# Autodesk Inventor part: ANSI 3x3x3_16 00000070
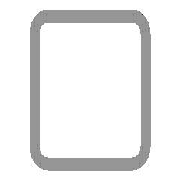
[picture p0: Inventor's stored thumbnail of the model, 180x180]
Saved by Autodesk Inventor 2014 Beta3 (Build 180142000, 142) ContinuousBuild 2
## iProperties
IsCustomPart: 1
_CCFamilyMember: 9
_CCFamilyDisplayName: ANSI AISC (Square) - Tube
_FrameMemberDoc: Frame Member File
_Version: 15.0.0
_GetPNFromCC: 1
Created: 2010-11
Part Number: ANSI 3x3x3_16 00000070
Material: Steel, Mild
Description: Tube
Document SubType Name: Modeling
Standard: ANSI
Designer: Beta-8540w
Standards Organization: ANSI
Language: en-US
Size Designation: 3x3x3/16
Categories: <MemberInstance><Categories><Category DisplayName="Structural Shapes" InternalName="089c4875-fa83-4c05-b084-43b9cc11f5ed" Mnemonic="GRDR"><CategoryParameter Dis
Stock Number: 3x3x3/16
Density: 7.86 g/cm^3
Appearance: Steel
G_L: 16.000 in
G_W: 3.000 in
G_H: 3.000 in
Author: Beta-8540w
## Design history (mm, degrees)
node "Start plane"
node "End plane"
sketch "Sketch"
  geometry: L1 (-38.1, -28.575)-(-38.1, 28.575); L2 (-28.575, 38.1)-(28.575, 38.1); L3 (38.1, 28.575)-(38.1, -28.575); L4 (28.575, -38.1)-(-28.575, -38.1); L5 (-28.575, 33.337)-(28.575, 33.338); L6 (33.338, 28.575)-(33.338, -28.575); L7 (28.575, -33.337)-(-28.575, -33.338); L8 (-33.338, -28.575)-(-33.338, 28.575); L9 (0, 56.102)-(0, -56.102) reference; L10 (-56.102, 0)-(56.102, 0) reference; A1 r 9.525 centre (-28.575, -28.575) between (-38.1, -28.575) and (-28.575, -38.1); A2 r 9.525 centre (-28.575, 28.575) between (-28.575, 38.1) and (-38.1, 28.575); A3 r 9.525 centre (28.575, 28.575) between (38.1, 28.575) and (28.575, 38.1); A4 r 9.525 centre (28.575, -28.575) between (28.575, -38.1) and (38.1, -28.575); A5 r 4.763 centre (-28.575, 28.575) between (-28.575, 33.337) and (-33.338, 28.575); A6 r 4.763 centre (28.575, 28.575) between (33.338, 28.575) and (28.575, 33.338); A7 r 4.763 centre (28.575, -28.575) between (28.575, -33.337) and (33.338, -28.575); A8 r 4.763 centre (-28.575, -28.575) between (-33.338, -28.575) and (-28.575, -33.338)
  constraints: 16 end point, 16 point on circle, 8 centre point, 8 tangent, 4 parallel, 3 equal radius, 2 perpendicular, 7 other
  dimensions: "d10" = 76.2 distance between parallel lines of L2 L4 (= G_H); "d11" = 76.2 distance between parallel lines of L1 L3 (= G_W); "d12" = 4.7625 distance between parallel lines of L3 L6 (= G_T); "d15" = 38.1 distance between parallel lines of L2 L10 (= 0.5 x d10); "d16" = 38.1 distance between parallel lines of L9 L3 (= 0.5 x d11); "d17" = 9.525 radius of A1 (= G_IR)
extrude "Body" new body sketch "Sketch" stored distance "d3" = 406.4 (= G_L); taper "d4" = 0 deg
node "Driven Length"
  sketch "Sketch3"
    geometry: L1 (0, 0)-(10, 0) reference
    constraints: 2 end point, 1 horizontal
  workplane "Work Plane3"
  sketch "Sketch4"
    geometry: L1 (-2, -114.3)-(12, -114.3) reference; L2 (-2, 292.1)-(12, 292.1) reference
    dimensions: "d19" = 406.4 distance between parallel lines of L1 L2 (derived)
workplane "Work Plane4"
split "Split1"
body "Solid1"
other parameters: "G_W" = 76.2 [user parameter; used in 1 equation term], "G_H" = 76.2 [user parameter; used in 1 equation term], "G_T" = 4.7625 [user parameter; used in 1 equation term], "G_IR" = 9.525 [user parameter; used in 1 equation term], "G_L" = 406.4 (= d19) [user parameter; used in 1 equation term], "G_OFFSET_START" = 114.3 [user parameter; used in 1 equation term], "G_OFFSET_END" = 38.1 [user parameter; used in 1 equation term], "d13" = -114.3 (= -G_OFFSET_START), "d14" = 292.1 (= G_OFFSET_END + B_L), "B_L" = 254 [user parameter; used in 1 equation term], "d18" = 90 deg
